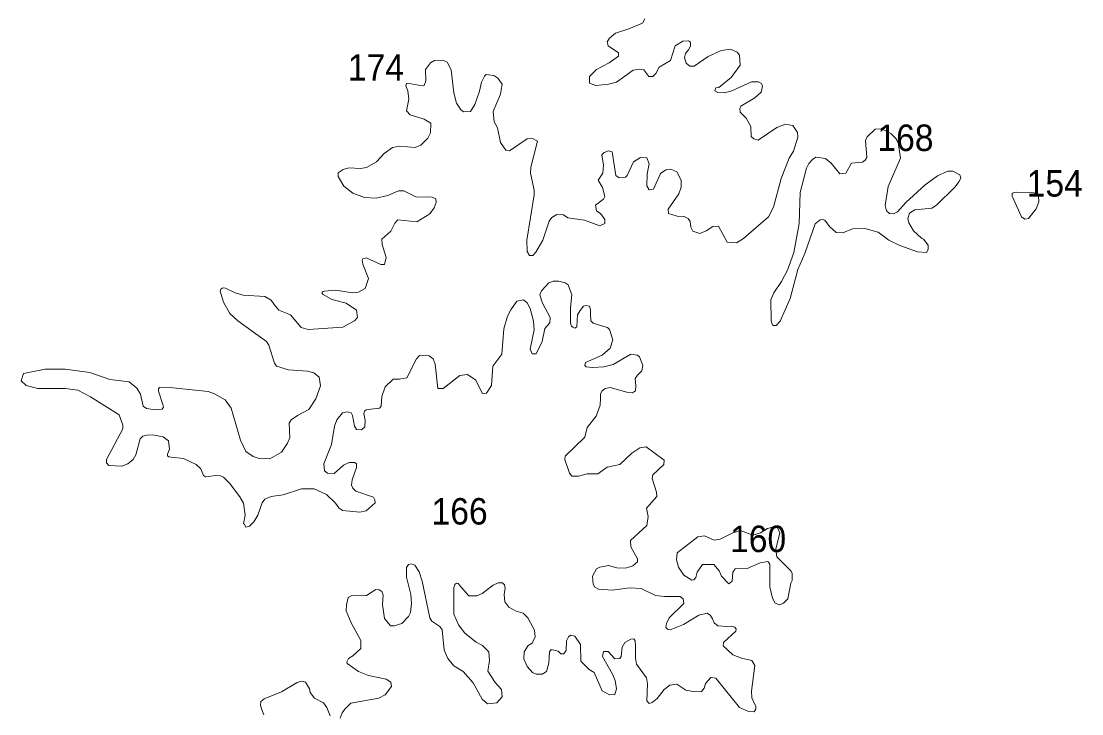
# Model space of a CAD drawing. Extents: x 499.9 to 555.3, y 9281.5 to 9336.8.
# Drawn here: x 524.34 to 530.75, y 9321.69 to 9325.88 of the extents above; entities that cross this region are included whole.
import ezdxf

# ---------------------------------------------------------------- set-up
doc = ezdxf.new("R2010")
doc.units = 0
doc.header["$LTSCALE"] = 0.064
doc.layers.add('2', color=7, linetype='Continuous', lineweight=13)
doc.layers.add('21', color=7, linetype='Continuous')

msp = doc.modelspace()

# ---------------------------------------------------------------- linework, layer by layer
at = {"layer": '2'}
for points in [[(528.9785, 9325.0515), (529.0042, 9325.0937), (529.0307, 9325.1782), (529.0293, 9325.2052), (529.0017, 9325.249), (528.9563, 9325.2566), (528.9046, 9325.2357), (528.7914, 9325.1604), (528.7644, 9325.1677), (528.7495, 9325.1823), (528.7473, 9325.2425), (528.7178, 9325.2927), (528.6828, 9325.3286), (528.6796, 9325.3489), (528.6854, 9325.3658), (528.7717, 9325.4166), (528.809, 9325.4489), (528.8176, 9325.486), (528.8122, 9325.503), (528.793, 9325.5115), (528.7518, 9325.5127), (528.6315, 9325.4575), (528.5877, 9325.4465), (528.5465, 9325.4479), (528.529, 9325.4572), (528.5359, 9325.4757), (528.5534, 9325.4785), (528.6288, 9325.5376), (528.6831, 9325.6123), (528.679, 9325.6737), (528.6633, 9325.6912), (528.6238, 9325.7104), (528.5671, 9325.7022), (528.4884, 9325.6659), (528.4045, 9325.6067), (528.3784, 9325.607), (528.3567, 9325.6262), (528.3466, 9325.6587), (528.3516, 9325.6833), (528.371, 9325.706), (528.3821, 9325.7279), (528.3826, 9325.7527), (528.3696, 9325.7595), (528.3349, 9325.7576), (528.2897, 9325.7293), (528.2619, 9325.6408), (528.193, 9325.6009), (528.173, 9325.5625), (528.1539, 9325.5437), (528.1303, 9325.5438), (528.0997, 9325.5844), (528.0758, 9325.5893), (528.0364, 9325.5836), (527.9344, 9325.5102), (527.8864, 9325.4982), (527.8094, 9325.491), (527.7723, 9325.5042), (527.7723, 9325.5448), (527.8135, 9325.5878), (527.8913, 9325.6267), (527.9467, 9325.6677), (527.9463, 9325.6868), (527.8835, 9325.7303), (527.8776, 9325.7549), (527.8916, 9325.7757), (527.9282, 9325.8073), (528.0101, 9325.8328), (528.0918, 9325.8673), (528.1059, 9325.8928)], [(526.7821, 9325.5189), (526.7794, 9325.587), (526.8097, 9325.6265), (526.8337, 9325.642), (526.8854, 9325.6434), (526.9109, 9325.6303), (526.9349, 9325.5856), (526.951, 9325.4456), (526.9683, 9325.3825), (526.9964, 9325.3417), (527.012, 9325.3302), (527.0523, 9325.3336), (527.0777, 9325.3756), (527.1067, 9325.4565), (527.1183, 9325.5106), (527.1364, 9325.5474), (527.1478, 9325.556), (527.1926, 9325.5514), (527.2177, 9325.5336), (527.2433, 9325.4986), (527.2346, 9325.4388), (527.1898, 9325.333), (527.1961, 9325.2713), (527.2154, 9325.2346), (527.2343, 9325.1447), (527.2668, 9325.0987), (527.2883, 9325.0948), (527.3955, 9325.1677), (527.4273, 9325.1706), (527.4565, 9325.1532), (527.4171, 9324.9967), (527.4159, 9324.9594), (527.4376, 9324.8582), (527.4379, 9324.83), (527.3933, 9324.555), (527.3951, 9324.4876), (527.4095, 9324.4616), (527.4287, 9324.4633), (527.4477, 9324.4824), (527.489, 9324.5558), (527.5276, 9324.6699), (527.5437, 9324.6921), (527.5741, 9324.7104), (527.6136, 9324.7076), (527.6416, 9324.6904), (527.7418, 9324.677), (527.8348, 9324.6421), (527.8652, 9324.6566), (527.8653, 9324.6797), (527.8404, 9324.714), (527.8144, 9324.7329), (527.8075, 9324.7674), (527.8563, 9324.8036), (527.8641, 9324.8193), (527.8502, 9324.8726), (527.8234, 9324.9189), (527.8513, 9324.9608), (527.8564, 9325.0078), (527.8468, 9325.0713), (527.8604, 9325.0861), (527.8867, 9325.0962), (527.908, 9325.09), (527.9307, 9324.9458), (527.9504, 9324.9326), (527.9894, 9324.9358), (527.9993, 9324.9453), (528.0371, 9325.0296), (528.0809, 9325.0544), (528.1185, 9325.0526), (528.1314, 9325.0174), (528.1206, 9324.9554), (528.1191, 9324.8829), (528.132, 9324.8596), (528.1575, 9324.8645), (528.2015, 9324.9584), (528.2336, 9324.9799), (528.2638, 9324.9845), (528.3, 9324.9686), (528.3256, 9324.9179), (528.3256, 9324.8758), (528.3111, 9324.8345), (528.247, 9324.7422), (528.2494, 9324.7158), (528.3006, 9324.7), (528.3433, 9324.698), (528.3672, 9324.6853), (528.3798, 9324.668), (528.3835, 9324.6345), (528.3967, 9324.6094), (528.438, 9324.5952), (528.4778, 9324.6112), (528.517, 9324.6374), (528.551, 9324.639), (528.6041, 9324.543), (528.6593, 9324.5392)], [(526.6612, 9325.4879), (526.6651, 9325.5014), (526.671, 9325.5053), (526.7605, 9325.4884), (526.7728, 9325.49), (526.7821, 9325.5189)], [(525.9564, 9323.4482), (525.9684, 9323.4686), (526.0061, 9323.4954), (526.0757, 9323.5306), (526.1164, 9323.5964), (526.1454, 9323.6747), (526.1375, 9323.7265), (526.1047, 9323.7523), (526.0666, 9323.7637), (525.9514, 9323.772), (525.8801, 9323.7944), (525.8677, 9323.8115), (525.8336, 9323.9206), (525.8202, 9323.9426), (525.6469, 9324.0666), (525.597, 9324.1109), (525.5596, 9324.1802), (525.5457, 9324.2264), (525.5395, 9324.247), (525.5428, 9324.2597), (525.5547, 9324.2672), (525.5708, 9324.2649), (525.6306, 9324.2365), (525.6778, 9324.2234), (525.8101, 9324.2148), (525.8466, 9324.1928), (525.8663, 9324.1656), (525.8942, 9324.1319), (525.9635, 9324.1032), (526.0297, 9324.0279), (526.0706, 9324.0159), (526.2814, 9324.0284), (526.3511, 9324.0667), (526.3684, 9324.0869), (526.3639, 9324.1326), (526.3015, 9324.1745), (526.2142, 9324.197), (526.1609, 9324.2258), (526.1557, 9324.232), (526.1551, 9324.2402), (526.1608, 9324.2451), (526.17, 9324.2471), (526.2354, 9324.2526), (526.3398, 9324.2367), (526.3753, 9324.2418), (526.4153, 9324.2634), (526.4365, 9324.3242), (526.4005, 9324.411), (526.3972, 9324.4339), (526.4016, 9324.4429), (526.4216, 9324.4479), (526.511, 9324.4074), (526.5334, 9324.4075), (526.5431, 9324.4505), (526.5182, 9324.5288), (526.5166, 9324.5621), (526.5714, 9324.6087), (526.5949, 9324.6589), (526.6135, 9324.6772), (526.7282, 9324.6667), (526.8059, 9324.7142), (526.8329, 9324.7507), (526.8454, 9324.7821), (526.8421, 9324.8045), (526.8206, 9324.8149), (526.7917, 9324.8175), (526.7249, 9324.8147), (526.6486, 9324.8527), (526.6167, 9324.854), (526.5529, 9324.8256), (526.4829, 9324.8097), (526.4122, 9324.8132), (526.3408, 9324.8386), (526.286, 9324.8808), (526.253, 9324.9403), (526.2523, 9324.9616), (526.2825, 9324.983), (526.3167, 9324.9924), (526.3875, 9324.988), (526.4239, 9324.9948), (526.4838, 9325.0288), (526.5309, 9325.0785), (526.581, 9325.1147), (526.6242, 9325.1232), (526.7184, 9325.1155), (526.7513, 9325.1304), (526.7947, 9325.1725), (526.8106, 9325.2045), (526.8135, 9325.2628), (526.7719, 9325.2873), (526.687, 9325.3123), (526.665, 9325.3375), (526.6786, 9325.4082), (526.6727, 9325.4583), (526.6612, 9325.4879)], [(528.6593, 9324.5392), (528.7031, 9324.5646), (528.8545, 9324.6959), (528.8844, 9324.7556), (528.9308, 9324.9274), (528.9785, 9325.0515)], [(528.0931, 9323.7982), (528.0742, 9323.8497), (528.0616, 9323.8593), (528.0221, 9323.8655), (527.9139, 9323.803), (527.858, 9323.7895), (527.7912, 9323.7864), (527.7521, 9323.7888), (527.7441, 9323.7978), (527.7477, 9323.8151), (527.8484, 9323.8596), (527.896, 9323.9026), (527.9118, 9323.9534), (527.8934, 9324.0143), (527.881, 9324.0281), (527.8435, 9324.0369), (527.7946, 9324.0531), (527.7803, 9324.0667), (527.778, 9324.1124), (527.7778, 9324.1334), (527.771, 9324.1552), (527.7492, 9324.1607), (527.7345, 9324.1563), (527.7149, 9324.1299), (527.6995, 9324.1035), (527.6948, 9324.0321), (527.682, 9324.024), (527.6716, 9324.0285), (527.6631, 9324.0354), (527.6577, 9324.0531), (527.6575, 9324.1467), (527.6652, 9324.2239), (527.6427, 9324.2853), (527.6249, 9324.2973), (527.5867, 9324.3082), (527.5516, 9324.3067), (527.5264, 9324.2966), (527.4814, 9324.2498), (527.4714, 9324.2248), (527.4881, 9324.1747), (527.5347, 9324.0885), (527.5315, 9324.0555), (527.501, 9324.0214), (527.4853, 9323.9423), (527.4488, 9323.8679), (527.4245, 9323.8677), (527.4127, 9323.897), (527.4379, 9324.0136), (527.4327, 9324.0665), (527.4135, 9324.1419), (527.3945, 9324.1766), (527.3722, 9324.1945), (527.3331, 9324.1855), (527.2963, 9324.1348), (527.2766, 9324.0949), (527.253, 9324.0185), (527.242, 9323.8667), (527.1875, 9323.794), (527.1784, 9323.6772), (527.1495, 9323.6306), (527.1307, 9323.6258), (527.1219, 9323.6297), (527.0852, 9323.7088), (527.0337, 9323.7433), (526.9885, 9323.7364), (526.8861, 9323.6579), (526.8547, 9323.6592), (526.8395, 9323.8061), (526.8272, 9323.8374), (526.8029, 9323.8559), (526.7446, 9323.8581), (526.7262, 9323.8381), (526.6679, 9323.7236), (526.6222, 9323.7147), (526.5845, 9323.7158), (526.5363, 9323.6686), (526.5166, 9323.6103), (526.5117, 9323.5523), (526.5017, 9323.5398), (526.4505, 9323.5328), (526.4216, 9323.5298), (526.4109, 9323.5209), (526.4072, 9323.5073), (526.4159, 9323.4655), (526.4144, 9323.4268), (526.3928, 9323.4077), (526.3635, 9323.4115), (526.3514, 9323.4303), (526.3399, 9323.496), (526.3302, 9323.5116), (526.3062, 9323.517), (526.2785, 9323.511), (526.2439, 9323.4688), (526.2299, 9323.4313), (526.2131, 9323.3198)], [(528.0487, 9323.6444), (528.0525, 9323.6753), (528.0474, 9323.7192), (528.062, 9323.7383), (528.0875, 9323.7657), (528.0931, 9323.7982)], [(526.2851, 9323.1953), (526.3186, 9323.211), (526.3532, 9323.2101), (526.3628, 9323.2038), (526.3628, 9323.1799), (526.338, 9323.106), (526.334, 9323.0736), (526.3409, 9323.055), (526.3593, 9323.0371), (526.4662, 9323.0008), (526.4747, 9322.9862), (526.476, 9322.9678), (526.4216, 9322.9188), (526.3835, 9322.911), (526.2784, 9322.9204), (526.2558, 9322.9361), (526.2363, 9322.9656), (526.1821, 9323.0183), (526.1065, 9323.0525), (526.0309, 9323.0525), (525.9206, 9323.0162), (525.8479, 9323.0059), (525.8092, 9322.9891), (525.7939, 9322.9668), (525.7663, 9322.8928), (525.7432, 9322.8528), (525.7163, 9322.8256), (525.6935, 9322.8207), (525.6872, 9322.8384), (525.6808, 9322.8405), (525.6902, 9322.8933), (525.6803, 9322.9657), (525.6588, 9323.0033), (525.5947, 9323.0859), (525.5596, 9323.1225), (525.5417, 9323.1304), (525.5125, 9323.1325), (525.4504, 9323.1246), (525.4376, 9323.1317), (525.4223, 9323.1724), (525.3936, 9323.1992), (525.3179, 9323.2354), (525.2428, 9323.243), (525.2297, 9323.2453), (525.2212, 9323.2523), (525.2212, 9323.2618), (525.2319, 9323.2912), (525.2259, 9323.3421), (525.1949, 9323.3668), (525.13, 9323.3787), (525.0958, 9323.3772), (525.072, 9323.3697), (525.056, 9323.3544), (525.0297, 9323.2579), (525.014, 9323.2298), (524.9813, 9323.2035), (524.9454, 9323.1881), (524.8667, 9323.1929), (524.853, 9323.2094), (524.8521, 9323.2302), (524.9516, 9323.4139), (524.9513, 9323.4362), (524.9289, 9323.4985), (524.7561, 9323.6071), (524.6781, 9323.6477), (524.6017, 9323.6589), (524.4368, 9323.6577), (524.3663, 9323.6764), (524.3365, 9323.7049), (524.3501, 9323.75), (524.4819, 9323.7761), (524.6017, 9323.7751), (524.7506, 9323.7545), (524.8723, 9323.7122), (524.9897, 9323.6979), (525.0356, 9323.661), (525.0575, 9323.6239), (525.0733, 9323.5524), (525.0941, 9323.5379), (525.1492, 9323.5301), (525.188, 9323.5335), (525.1958, 9323.5451), (525.1934, 9323.5608), (525.1672, 9323.6415), (525.1663, 9323.6557), (525.1724, 9323.6636), (525.2154, 9323.6659), (525.4668, 9323.6399), (525.5058, 9323.627), (525.5687, 9323.5908), (525.6056, 9323.5393), (525.663, 9323.3462), (525.6951, 9323.278), (525.7381, 9323.2468), (525.7755, 9323.2358)], [(528.2987, 9321.8712), (528.3544, 9321.8349), (528.408, 9321.8256), (528.4488, 9321.8275), (528.4656, 9321.8473), (528.4735, 9321.8747), (528.5059, 9321.9112), (528.5359, 9321.9079), (528.6774, 9321.7309), (528.7327, 9321.7049), (528.7675, 9321.7031), (528.777, 9321.7196), (528.7776, 9321.7361), (528.7527, 9321.7889), (528.7509, 9321.8287), (528.7708, 9321.9837), (528.7523, 9322.0146), (528.6913, 9322.028), (528.6379, 9322.0484), (528.5793, 9322.1034), (528.5814, 9322.1234), (528.6565, 9322.1907), (528.6582, 9322.2043), (528.65, 9322.2155), (528.6275, 9322.2223), (528.6027, 9322.2188), (528.5474, 9322.2237), (528.5249, 9322.2428), (528.5143, 9322.2659), (528.5032, 9322.2871), (528.4827, 9322.3), (528.4319, 9322.2881), (528.3402, 9322.2314), (528.2894, 9322.2113), (528.2599, 9322.1989), (528.2429, 9322.2033), (528.2329, 9322.2138), (528.2374, 9322.2385), (528.2533, 9322.2712), (528.255, 9322.2747), (528.3414, 9322.3588), (528.3382, 9322.387), (528.3193, 9322.4007), (528.2249, 9322.4001), (528.1707, 9322.4079), (528.0838, 9322.4496), (528.014, 9322.4525), (527.9097, 9322.44), (527.8269, 9322.4446), (527.8041, 9322.4574), (527.7945, 9322.4765), (527.7888, 9322.523), (527.8147, 9322.568), (527.8344, 9322.5791), (527.8866, 9322.5876), (527.9376, 9322.5751), (527.9885, 9322.5721), (528.0345, 9322.5864), (528.0613, 9322.6103), (528.0608, 9322.6278), (528.0206, 9322.7009), (528.019, 9322.7387), (528.119, 9322.8306), (528.1268, 9322.8846), (528.1163, 9322.9346), (528.1777, 9323.0056), (528.1763, 9323.0327), (528.1495, 9323.1139), (528.1535, 9323.1375), (528.2208, 9323.1986), (528.2237, 9323.2251), (528.1134, 9323.3049), (528.0767, 9323.3001), (528.0274, 9323.2679), (527.9559, 9323.199), (527.8779, 9323.1831), (527.8224, 9323.1433), (527.7569, 9323.1417), (527.706, 9323.1292), (527.6657, 9323.1275), (527.6506, 9323.1468), (527.6227, 9323.2292), (527.624, 9323.25), (527.7427, 9323.364), (527.7569, 9323.4229), (527.8111, 9323.4905), (527.8371, 9323.5582), (527.8376, 9323.5977), (527.8372, 9323.625), (527.8462, 9323.6418), (527.8665, 9323.6576), (527.897, 9323.6635), (527.9981, 9323.6369), (528.0319, 9323.6315), (528.0487, 9323.6444)], [(525.7755, 9323.2358), (525.8384, 9323.2325), (525.9097, 9323.2741), (525.946, 9323.3273), (525.9601, 9323.3597), (525.9564, 9323.4482)], [(526.2131, 9323.3198), (526.1651, 9323.2038), (526.1694, 9323.1616), (526.1873, 9323.146), (526.229, 9323.1449), (526.2851, 9323.1953)], [(526.6912, 9322.4135), (526.6646, 9322.5171), (526.6645, 9322.5757), (526.6779, 9322.5939), (526.696, 9322.5979), (526.7156, 9322.5902)], [(526.7156, 9322.5902), (526.7424, 9322.5503), (526.76, 9322.4947), (526.8059, 9322.2719), (526.818, 9322.2527), (526.8668, 9322.2198), (526.8804, 9322.1993), (526.8935, 9322.0761), (526.9156, 9322.0252), (526.9514, 9321.9827), (527.0074, 9321.9484), (527.0681, 9321.8787), (527.1235, 9321.7799), (527.1549, 9321.7523), (527.2113, 9321.7583), (527.2437, 9321.7935), (527.2407, 9321.8382), (527.2019, 9321.8819), (527.1567, 9321.9505), (527.1672, 9322.0132), (527.1634, 9322.0675), (527.1258, 9322.1039), (527.0862, 9322.1242), (527.018, 9322.1801), (526.9799, 9322.2307), (526.9512, 9322.2952), (526.9509, 9322.454), (526.9571, 9322.4735), (526.967, 9322.4822), (526.978, 9322.4796), (526.9976, 9322.4552), (527.0427, 9322.4055), (527.0909, 9322.4051), (527.1236, 9322.4189), (527.1902, 9322.4702), (527.2193, 9322.4844), (527.2457, 9322.4833), (527.2583, 9322.4722), (527.2624, 9322.4509), (527.2565, 9322.4127), (527.2597, 9322.3697), (527.2845, 9322.3363), (527.3276, 9322.3118), (527.371, 9322.3012), (527.3989, 9322.2711), (527.439, 9322.197), (527.4438, 9322.1574), (527.4251, 9322.1186), (527.4016, 9322.1053), (527.3773, 9322.0667), (527.3742, 9322.0245), (527.3945, 9321.9784), (527.4268, 9321.9418), (527.4489, 9321.9307), (527.4864, 9321.9321), (527.5127, 9321.9471), (527.5251, 9321.9982), (527.53, 9322.0657), (527.539, 9322.0805), (527.5817, 9322.0715), (527.5988, 9322.055), (527.6165, 9322.0554), (527.6305, 9322.0752), (527.6323, 9322.1326), (527.6445, 9322.1573), (527.6576, 9322.1672), (527.6834, 9322.1618), (527.7177, 9322.1103), (527.7195, 9322.0094), (527.769, 9321.9588), (527.8004, 9321.9415), (527.849, 9321.83), (527.8917, 9321.8074), (527.9239, 9321.8095), (527.9344, 9321.8435), (527.9268, 9321.8922), (527.9105, 9321.9321), (527.8496, 9322.0391), (527.8557, 9322.0678), (527.8854, 9322.0682), (527.9249, 9322.0232), (527.9558, 9322.026), (527.9634, 9322.0379), (527.97, 9322.0951), (527.9851, 9322.1223), (528.0208, 9322.143), (528.039, 9322.1445), (528.048, 9322.1338), (528.049, 9322.1033), (528.0491, 9322.0276), (528.0551, 9321.9912), (528.1156, 9321.9097), (528.1221, 9321.8724), (528.1191, 9321.7696), (528.1325, 9321.7543)], [(526.2638, 9321.6655), (526.2756, 9321.6983), (526.2937, 9321.7203), (526.3286, 9321.7552), (526.4977, 9321.7861), (526.536, 9321.8073), (526.5748, 9321.8565), (526.57, 9321.8824), (526.5431, 9321.9015), (526.4359, 9321.924), (526.375, 9321.9473), (526.3075, 9321.9969), (526.3051, 9322.0059), (526.3145, 9322.0258), (526.3406, 9322.0416), (526.3894, 9322.0874), (526.3903, 9322.1358), (526.3302, 9322.2409), (526.3017, 9322.3134), (526.3018, 9322.351), (526.3119, 9322.3954), (526.331, 9322.4046), (526.4232, 9322.4064), (526.4791, 9322.4438), (526.4996, 9322.4413), (526.5167, 9322.432), (526.5238, 9322.4095), (526.5197, 9322.3535), (526.5332, 9322.2689), (526.5696, 9322.2236), (526.5912, 9322.2235), (526.638, 9322.2375), (526.6769, 9322.2807), (526.6894, 9322.304), (526.696, 9322.3578), (526.6912, 9322.4135)], [(525.8023, 9321.6855), (525.795, 9321.706), (525.7829, 9321.7419), (525.7857, 9321.7665), (525.8057, 9321.7828), (525.9099, 9321.8255), (526.0038, 9321.8802), (526.0248, 9321.8864), (526.0372, 9321.8889), (526.0544, 9321.8822), (526.0785, 9321.8429), (526.084, 9321.8216), (526.1094, 9321.7872), (526.1639, 9321.7573), (526.1829, 9321.7297), (526.2043, 9321.6798)], [(528.1325, 9321.7543), (528.1514, 9321.7608), (528.1797, 9321.7845), (528.2235, 9321.8392), (528.2568, 9321.8653), (528.2987, 9321.8712)]]:
    msp.add_lwpolyline(points, dxfattribs=at)
for points in [[(529.8759, 9324.945), (529.8015, 9324.8906), (529.6834, 9324.7825), (529.6344, 9324.7265), (529.6089, 9324.7145), (529.5849, 9324.7157), (529.5674, 9324.7333), (529.5596, 9324.7646), (529.5773, 9324.8801), (529.6523, 9325.0516), (529.637, 9325.1466), (529.624, 9325.1698), (529.5927, 9325.201), (529.5387, 9325.2282), (529.498, 9325.2265), (529.4494, 9325.18), (529.4404, 9325.1587), (529.4475, 9325.0552), (529.4382, 9325.0385), (529.4219, 9325.0277), (529.3546, 9325.0212), (529.3213, 9324.9594), (529.2841, 9324.9562), (529.233, 9325.021), (529.1987, 9325.0479), (529.139, 9325.0563), (529.1186, 9325.0435), (529.0968, 9325.0186), (529.0832, 9324.9905), (529.0453, 9324.8439), (529.0388, 9324.6561), (529.0068, 9324.4811), (528.9691, 9324.3739), (528.933, 9324.3052), (528.8859, 9324.2375), (528.8672, 9324.1953), (528.8706, 9324.0666), (528.8744, 9324.0527), (528.8805, 9324.0399), (528.8994, 9324.0401), (528.9241, 9324.0665), (528.9856, 9324.2033), (529.0305, 9324.3783), (529.0725, 9324.4746), (529.1353, 9324.6543), (529.1658, 9324.6771), (529.1821, 9324.6805), (529.1947, 9324.6757), (529.2225, 9324.6386), (529.2619, 9324.6015), (529.3031, 9324.5998), (529.3621, 9324.6236), (529.4354, 9324.6255), (529.5174, 9324.6029), (529.5808, 9324.5547), (529.6485, 9324.5225), (529.7544, 9324.4852), (529.8089, 9324.4814), (529.818, 9324.4985), (529.8183, 9324.5253), (529.7905, 9324.5622), (529.7779, 9324.5664), (529.7309, 9324.6114), (529.701, 9324.6593), (529.6952, 9324.6871), (529.7056, 9324.7187), (529.7372, 9324.7393), (529.8403, 9324.7492), (529.8697, 9324.7667), (529.9798, 9324.8752), (530.0061, 9324.9093), (530.0157, 9324.9321), (530.0096, 9324.951), (529.9684, 9324.9718), (529.9383, 9324.9718)], [(530.4713, 9324.7443), (530.4868, 9324.7864), (530.4865, 9324.8202), (530.4755, 9324.8357), (530.4574, 9324.8414), (530.3499, 9324.8458), (530.3272, 9324.8395), (530.326, 9324.8218), (530.3837, 9324.6955), (530.4036, 9324.6828), (530.4245, 9324.6856)], [(528.5231, 9322.5936), (528.5557, 9322.5569), (528.5704, 9322.5242), (528.6136, 9322.478), (528.6339, 9322.4931), (528.6372, 9322.5487), (528.6523, 9322.5685), (528.7249, 9322.5708), (528.804, 9322.6049), (528.8503, 9322.6136), (528.8627, 9322.5971), (528.8611, 9322.4585), (528.8772, 9322.3913), (528.8944, 9322.3604), (528.9197, 9322.3514), (528.9452, 9322.3617), (528.9706, 9322.3873), (528.9887, 9322.4819), (528.9973, 9322.4972), (528.9974, 9322.5415), (528.9896, 9322.5562), (528.9034, 9322.6414), (528.8977, 9322.6866), (528.9226, 9322.7852), (528.9076, 9322.8155), (528.8854, 9322.8215), (528.8466, 9322.8126), (528.8049, 9322.7853), (528.7583, 9322.7727), (528.6838, 9322.799), (528.6387, 9322.7869), (528.5606, 9322.7475), (528.5247, 9322.7418), (528.4674, 9322.7673), (528.4264, 9322.762), (528.3011, 9322.6645), (528.2974, 9322.6236), (528.3106, 9322.5777), (528.3425, 9322.5301), (528.3898, 9322.4992), (528.4026, 9322.501), (528.4136, 9322.5157), (528.4234, 9322.5487), (528.4537, 9322.5937)]]:
    msp.add_lwpolyline(points, close=True, dxfattribs=at)

# ---------------------------------------------------------------- texts
at = {"layer": '21', "width": 0.95}
for s, p in [('174', (526.3113, 9325.5196)), ('168', (529.512, 9325.0943)), ('154', (530.4142, 9324.8185)), ('166', (526.817, 9322.8361)), ('160', (528.6213, 9322.6694))]:
    msp.add_text(s, height=0.16, dxfattribs=at).set_placement(p)

doc.saveas('drawing.dxf')
